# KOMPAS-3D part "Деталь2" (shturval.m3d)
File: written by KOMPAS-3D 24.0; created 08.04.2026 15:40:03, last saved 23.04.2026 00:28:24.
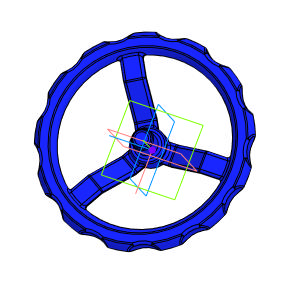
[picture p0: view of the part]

Document properties: Автор: R2D2; Полное имя файла: C:\Работа\VSO2130M-F-S Клапан запорный DN.ru\DN15\исходные материалы\shturval.m3d

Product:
- Body: Твердое тело1  | qty 1
    Масса: 0.594157
- Part/product: Деталь2
    Масса: 0.594157
    additional columns: Типовые

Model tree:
1. Твердое тело1  (labels: Твердое тело1)
2. Масштабирование:1
3. Масштабирование : Твердое тело1
     Масштаб по оси Х = 1; Масштаб по оси Y = 1; Масштаб по оси Z = 1; Коэффициент = 0.95

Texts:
  Масштабирование : Вершина.Начало координат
